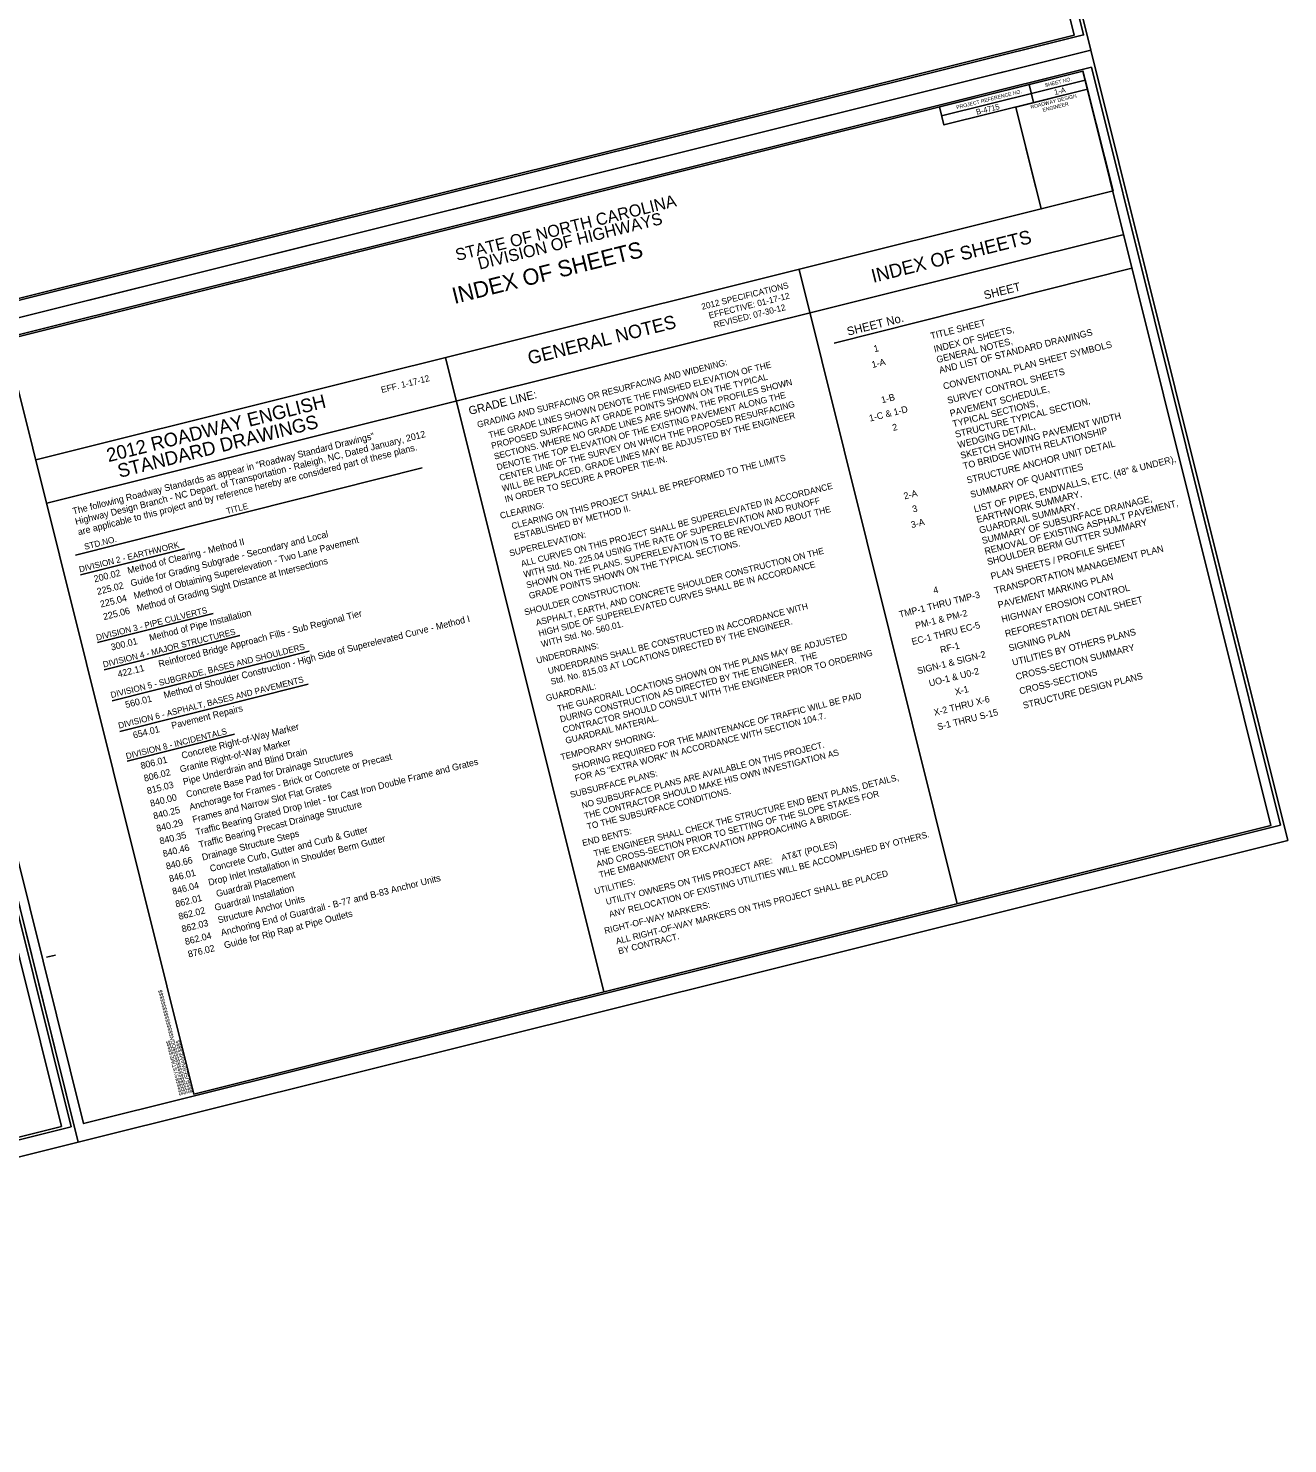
# Model space of a CAD drawing. Extents: x 1030323 to 1034123, y 654802 to 657751.
# Drawn here: x 1032422 to 1034123, y 654802 to 656713 of the extents above; entities that cross this region are included whole.
import ezdxf

# ---------------------------------------------------------------- set-up
doc = ezdxf.new("R2010")
doc.units = 0
for name, color, linetype in [('Default', 7, 'Continuous'), ('Old_Level_40', 7, 'Continuous'), ('Sheet Cutting Line CELL', 7, 'Continuous'), ('Sheet Data Field CELL', 7, 'Continuous'), ('Sheet Plan CELL', 7, 'Continuous'), ('Sheet Plot Border Inside CELL', 7, 'Continuous'), ('Sheet Plot Border Outside CELL', 7, 'Continuous'), ('Sheet Summary CELL', 7, 'Continuous'), ('Sheet Symbology CELL', 7, 'Continuous')]:
    doc.layers.add(name, color=color, linetype=linetype)

msp = doc.modelspace()

# ---------------------------------------------------------------- linework, layer by layer
at = {"layer": 'Old_Level_40'}
for p, q in [((1033510.2, 656288.1), (1033912.5, 656389.2)), ((1032485.4, 656001.8), (1032953.8, 656119.5)), ((1032492.1, 655975.1), (1032632.6, 656010.4)), ((1032515.1, 655883.6), (1032671.3, 655922.8)), ((1032524.3, 655847.1), (1032707.4, 655893.1)), ((1032534.8, 655805), (1032801.1, 655871.9)), ((1032545.2, 655763.8), (1032799.6, 655827.7)), ((1032555.3, 655723.6), (1032700.3, 655760))]:
    msp.add_line(p, q, dxfattribs=at)
at = {"layer": 'Sheet Cutting Line CELL'}
for p, q in [((1032223.1, 656276.4), (1033857.1, 656683.8)), ((1033857.1, 656683.8), (1032223.1, 656276.4)), ((1032223.1, 656276.4), (1032489.2, 655209.1)), ((1032489.2, 655209.1), (1034123.2, 655616.5)), ((1030855.2, 654801.7), (1032489.2, 655209.1))]:
    msp.add_line(p, q, dxfattribs=at)
at = {"layer": 'Sheet Plan CELL'}
for p, q in [((1033755.7, 656606.8), (1033783.1, 656497.7)), ((1032431.8, 656130.6), (1033790.2, 656469.3)), ((1032446.6, 656071.9), (1033902, 656434.8)), ((1033676.8, 655531), (1033463.1, 656387.8)), ((1033199.1, 655411.9), (1032985.5, 656268.7))]:
    msp.add_line(p, q, dxfattribs=at)
msp.add_lwpolyline([(1033755.7, 656606.8), (1033852.7, 656631.2), (1033887.2, 656493.7), (1033790.2, 656469.3)], close=True, dxfattribs=at)
at = {"layer": 'Sheet Plot Border Inside CELL'}
for points in [[(1033592, 657728.3), (1031975, 657325.1), (1032230.3, 656301.4), (1033847.3, 656704.5)], [(1033858.1, 656661), (1032241.1, 656257.8), (1032496.4, 655234), (1034113.4, 655637.2)], [(1030862.4, 654826.7), (1032479.4, 655229.8), (1032224.1, 656253.6), (1030607.1, 655850.4)]]:
    msp.add_lwpolyline(points, close=True, dxfattribs=at)
at = {"layer": 'Sheet Plot Border Outside CELL'}
for points in [[(1033590.9, 657751.2), (1031957, 657343.8), (1032223.1, 656276.4), (1033857.1, 656683.8)], [(1033857.1, 656683.8), (1032223.1, 656276.4), (1032489.2, 655209.1), (1034123.2, 655616.5)], [(1030855.2, 654801.7), (1032489.2, 655209.1), (1032223.1, 656276.4), (1030589.1, 655869)]]:
    msp.add_lwpolyline(points, close=True, dxfattribs=at)
at = {"layer": 'Sheet Summary CELL'}
for p, q in [((1033655.5, 656594.9), (1033849.6, 656643.3)), ((1033658.6, 656582.8), (1033852.7, 656631.2)), ((1033773.8, 656637.3), (1033779.9, 656613)), ((1033140, 656387.8), (1033140, 656387.8)), ((1032446.1, 655458.6), (1032458.2, 655461.6)), ((1032645.2, 655273.8), (1032645.2, 655273.8)), ((1032645.2, 655273.8), (1032645.2, 655273.8)), ((1032645.2, 655273.8), (1032645.2, 655273.8)), ((1032645.2, 655273.8), (1032645.2, 655273.8)), ((1032645.2, 655273.8), (1032645.2, 655273.8)), ((1032645.2, 655273.8), (1032645.2, 655273.8))]:
    msp.add_line(p, q, dxfattribs=at)
for points in [[(1033580.5, 657722.8), (1032125.1, 657359.9), (1032379.1, 656341.1), (1033834.5, 656704)], [(1033846.6, 656655.5), (1032391.2, 656292.6), (1032645.2, 655273.8), (1034100.6, 655636.7)], [(1033652.5, 656607.1), (1033846.6, 656655.5), (1033852.7, 656631.2), (1033658.6, 656582.8)]]:
    msp.add_lwpolyline(points, close=True, dxfattribs=at)
for points in [[(1032512.5, 656374.4), (1032512.5, 656374.4)], [(1032778.6, 655307), (1032778.6, 655307)]]:
    msp.add_lwpolyline(points, dxfattribs=at)
at = {"layer": 'Sheet Symbology CELL'}
msp.add_lwpolyline([(1032212.6, 656248.1), (1030757.2, 655885.2), (1031011, 654867.4), (1032466.4, 655230.3)], close=True, dxfattribs=at)

# ---------------------------------------------------------------- texts
at = {"layer": 'Default'}
for s, height, p in [('SHEET', 11.35, (1033714.1, 656347.1)), ('SHEET No.', 11.35, (1033529.3, 656298.1)), ('TITLE SHEET', 9, (1033641.8, 656293.3)), ('INDEX OF SHEETS,', 9, (1033646.2, 656275.5)), ('AND LIST OF STANDARD DRAWINGS', 9, (1033653.4, 656247)), ('1', 9, (1033565, 656275.8)), ('GENERAL NOTES,', 9, (1033649.8, 656261.2)), ('CONVENTIONAL PLAN SHEET SYMBOLS', 9, (1033658.8, 656225.3)), ('GRADING AND SURFACING OR RESURFACING AND WIDENING:  ', 8.5, (1033029.2, 656173.7)), ('THE GRADE LINES SHOWN DENOTE THE FINISHED ELEVATION OF THE', 8.5, (1033044.7, 656159.6)), ('1-A', 9, (1033562.3, 656254.5)), ('PROPOSED SURFACING AT GRADE POINTS SHOWN ON THE TYPICAL', 8.5, (1033048.3, 656145.2)), ('SECTIONS. WHERE NO GRADE LINES ARE SHOWN, THE PROFILES SHOWN', 8.5, (1033052, 656130.7)), ('SURVEY CONTROL SHEETS', 9, (1033664.5, 656206.1)), ('GRADE LINE:  ', 11.124, (1033018.1, 656191.1)), ('DENOTE THE TOP ELEVATION OF THE EXISTING PAVEMENT ALONG THE', 8.5, (1033055.6, 656116.3)), ('1-B', 9, (1033575.1, 656206.8)), ('PAVEMENT SCHEDULE,', 9, (1033667.9, 656188.8)), ('CENTER LINE OF THE SURVEY ON WHICH THE PROPOSED RESURFACING', 8.5, (1033059.2, 656101.9)), ('1-C & 1-D', 9, (1033558.8, 656182.1)), ('TYPICAL SECTIONS,', 9, (1033671.5, 656174.5)), ('STRUCTURE TYPICAL SECTION,', 9, (1033675, 656160.3)), ('WILL BE REPLACED. GRADE LINES MAY BE ADJUSTED BY THE ENGINEER', 8.5, (1033062.8, 656087.5)), ('SKETCH SHOWING PAVEMENT WIDTH', 9, (1033682.2, 656131.8)), ('2', 9, (1033590.2, 656169.4)), ('WEDGING DETAIL,', 9, (1033678.6, 656146.1)), ('TO BRIDGE WIDTH RELATIONSHIP', 9, (1033685.8, 656117.6)), ('STRUCTURE ANCHOR UNIT DETAIL', 9, (1033690.6, 656098.3)), ('IN ORDER TO SECURE A PROPER TIE-IN.', 8.5, (1033066.5, 656073)), ('CLEARING ON THIS PROJECT SHALL BE PREFORMED TO THE LIMITS', 8.5, (1033075.6, 656036.7)), ('SUMMARY OF QUANTITIES', 9, (1033695.5, 656079)), ('LIST OF PIPES, ENDWALLS, ETC. (48" & UNDER), ', 9, (1033700.3, 656059.4)), ('ALL CURVES ON THIS PROJECT SHALL BE SUPERELEVATED IN ACCORDANCE', 8.5, (1033088.4, 655985.9)), ('2-A', 9, (1033605.5, 656077)), ('EARTHWORK SUMMARY,', 9, (1033703.9, 656045.2)), ('CLEARING:', 8.5, (1033060.1, 656050.8)), ('ESTABLISHED BY METHOD II.', 8.5, (1033079.2, 656022.2)), ('WITH Std. No. 225.04 USING THE RATE OF SUPERELEVATION AND RUNOFF', 8.5, (1033092, 655971.4)), ('SHOWN ON THE PLANS. SUPERELEVATION IS TO BE REVOLVED ABOUT THE', 8.5, (1033095.6, 655957)), ('3', 9, (1033617.2, 656059.3)), ('GUARDRAIL SUMMARY,', 9, (1033707.5, 656030.9)), ('SUMMARY OF SUBSURFACE DRAINAGE,', 9, (1033711.1, 656016.7)), ('REMOVAL OF EXISTING ASPHALT PAVEMENT,', 9, (1033714.7, 656002.5)), ('3-A', 9, (1033615.2, 656038.2)), ('SHOULDER BERM GUTTER SUMMARY', 9, (1033718.2, 655988.2)), ('SUPERELEVATION:', 8.5, (1033072.8, 656000)), ('GRADE POINTS SHOWN ON THE TYPICAL SECTIONS.', 8.5, (1033099.2, 655942.6)), ('ASPHALT, EARTH, AND CONCRETE SHOULDER CONSTRUCTION ON THE', 8.5, (1033108.4, 655906.2)), ('PLAN SHEETS / PROFILE SHEET', 9, (1033723.1, 655968.8)), ('TRANSPORTATION MANAGEMENT PLAN', 9, (1033727.9, 655949.4)), ('HIGH SIDE OF SUPERELEVATED CURVES SHALL BE IN ACCORDANCE', 8.5, (1033112, 655891.8)), ('PAVEMENT MARKING PLAN', 9, (1033732.7, 655930)), ('SHOULDER CONSTRUCTION:', 8.5, (1033092.9, 655920.4)), ('TMP-1 THRU TMP-3', 9, (1033599.2, 655917.2)), ('4', 9, (1033645.4, 655949.5)), ('HIGHWAY EROSION CONTROL', 9, (1033737.6, 655910.6)), ('UNDERDRAINS SHALL BE CONSTRUCTED IN ACCORDANCE WITH', 8.5, (1033124.8, 655841)), ('REFORESTATION DETAIL SHEET', 9, (1033742.4, 655891.2)), ('Std. No. 815.03 AT LOCATIONS DIRECTED BY THE ENGINEER.', 8.5, (1033128.4, 655826.6)), ('PM-1 & PM-2', 9, (1033621.2, 655902.1)), ('WITH Std. No. 560.01.', 8.5, (1033115.6, 655877.4)), ('THE GUARDRAIL LOCATIONS SHOWN ON THE PLANS MAY BE ADJUSTED', 8.5, (1033137.5, 655790.2)), ('EC-1 THRU EC-5', 9, (1033616.3, 655880.3)), ('SIGNING PLAN', 9, (1033747.3, 655871.8)), ('UTILITIES BY OTHERS PLANS', 9, (1033752.1, 655852.4)), ('UNDERDRAINS:', 8.5, (1033109.2, 655855.1)), ('RF-1 ', 9, (1033654.8, 655869.3)), ('CROSS-SECTION SUMMARY', 9, (1033756.9, 655833)), ('DURING CONSTRUCTION AS DIRECTED BY THE ENGINEER.  THE', 8.5, (1033141.1, 655775.8)), ('CONTRACTOR SHOULD CONSULT WITH THE ENGINEER PRIOR TO ORDERING', 8.5, (1033144.8, 655761.3)), ('SIGN-1 & SIGN-2', 9, (1033623.8, 655840.9)), ('UO-1 & U0-2', 9, (1033639.6, 655824.3)), ('CROSS-SECTIONS', 9, (1033761.8, 655813.6)), ('STRUCTURE DESIGN PLANS', 9, (1033766.6, 655794.2)), ('GUARDRAIL: ', 8.5, (1033122, 655804.3)), ('X-1', 9, (1033674.7, 655812.5)), ('SHORING REQUIRED FOR THE MAINTENANCE OF TRAFFIC WILL BE PAID', 8.5, (1033157.5, 655710.5)), ('X-2 THRU X-6', 9, (1033646.1, 655784.7)), ('GUARDRAIL MATERIAL.', 8.5, (1033148.4, 655746.9)), ('FOR AS "EXTRA WORK" IN ACCORDANCE WITH SECTION 104.7.', 8.5, (1033161.2, 655696.1)), ('S-1 THRU S-15', 9, (1033650.9, 655765.3)), ('TEMPORARY SHORING:', 8.5, (1033142, 655724.7)), ('NO SUBSURFACE PLANS ARE AVAILABLE ON THIS PROJECT.', 8.5, (1033170.3, 655659.7)), ('THE CONTRACTOR SHOULD MAKE HIS OWN INVESTIGATION AS', 8.5, (1033173.9, 655645.3)), ('SUBSURFACE PLANS:  ', 8.5, (1033154.8, 655673.9)), ('THE ENGINEER SHALL CHECK THE STRUCTURE END BENT PLANS, DETAILS,', 8.5, (1033186.7, 655594.5)), ('TO THE SUBSURFACE CONDITIONS.', 8.5, (1033177.5, 655630.9)), ('AND CROSS-SECTION PRIOR TO SETTING OF THE SLOPE STAKES FOR', 8.5, (1033190.3, 655580.1)), ('THE EMBANKMENT OR EXCAVATION APPROACHING A BRIDGE.', 8.5, (1033193.9, 655565.7)), ('END BENTS:', 8.5, (1033171.2, 655608.7))]:
    msp.add_text(s, height=height, rotation=14.1042, dxfattribs=at).set_placement(p)
at = {"layer": 'Old_Level_40'}
for s, height, p in [('2012 SPECIFICATIONS', 8.343, (1033332.2, 656333.1)), ('EFFECTIVE: 01-17-12', 8.343, (1033342.1, 656321.2)), ('REVISED: 07-30-12', 8.343, (1033348.6, 656308.5)), ('EFF. 1-17-12', 8.512, (1032899.4, 656220.7)), ('The following Roadway Standards as appear in "Roadway Standard Drawings"', 9, (1032482.6, 656056.6)), ('Highway Design Branch - NC Depart. of Transportation - Raleigh, NC, Dated January, 2012', 9, (1032486.1, 656042.6)), ('are applicable to this project and by reference hereby are considered part of these plans.', 9, (1032489.6, 656028.5)), ('STD.NO.                                                  TITLE', 8.243, (1032498.3, 656008.9)), ('225.02   Guide for Grading Subgrade - Secondary and Local', 9, (1032515.5, 655948)), ('DIVISION 2 - EARTHWORK', 8.243, (1032491.3, 655978.4)), ('200.02   Method of Clearing - Method II', 9, (1032511.3, 655965)), ('225.04   Method of Obtaining Superelevation - Two Lane Pavement', 9, (1032519.8, 655931)), ('225.06   Method of Grading Sight Distance at Intersections', 9, (1032524, 655914)), ('DIVISION 3 - PIPE CULVERTS', 8.243, (1032514.4, 655886.3)), ('300.01     Method of Pipe Installation', 9, (1032534.3, 655872.8)), ('422.11      Reinforced Bridge Approach Fills - Sub Regional Tier', 9, (1032543.5, 655836.5)), ('560.01     Method of Shoulder Construction - High Side of Superelevated Curve - Method I', 9, (1032553.8, 655795.2)), ('DIVISION 4 - MAJOR STRUCTURES', 8.243, (1032523.5, 655849.9)), ('DIVISION 5 - SUBGRADE, BASES AND SHOULDERS', 8.243, (1032533.9, 655808.7)), ('DIVISION 6 - ASPHALT, BASES AND PAVEMENTS', 8.243, (1032544.3, 655767.4)), ('654.01     Pavement Repairs', 9, (1032564.2, 655754)), ('DIVISION 8 - INCIDENTALS', 8.243, (1032554.6, 655726.2)), ('806.01      Concrete Right-of-Way Marker', 9, (1032574.6, 655712.8)), ('806.02    Granite Right-of-Way Marker', 9, (1032578.9, 655695.8)), ('815.03    Pipe Underdrain and Blind Drain', 9, (1032583.1, 655678.9)), ('840.00    Concrete Base Pad for Drainage Structures', 9, (1032587.4, 655661.9)), ('840.25    Anchorage for Frames - Brick or Concrete or Precast', 9, (1032591.7, 655644.9)), ('840.35    Traffic Bearing Grated Drop Inlet - for Cast Iron Double Frame and Grates', 9, (1032600.2, 655611)), ('840.29    Frames and Narrow Slot Flat Grates', 9, (1032595.9, 655628)), ('840.46    Traffic Bearing Precast Drainage Structure', 9, (1032604.5, 655594)), ('840.66    Drainage Structure Steps', 9, (1032608.7, 655577)), ('846.01      Concrete Curb, Gutter and Curb & Gutter', 9, (1032613, 655560.1)), ('ANY RELOCATION OF EXISTING UTILITIES WILL BE ACCOMPLISHED BY OTHERS.', 8.5, (1033207.3, 655512.3)), ('846.04    Drop Inlet Installation in Shoulder Berm Gutter', 9, (1032617.3, 655543.1)), ('UTILITY OWNERS ON THIS PROJECT ARE:    AT&T (POLES)', 8.5, (1033203.1, 655529.3)), ('862.01      Guardrail Placement', 9, (1032621.5, 655526.1)), ('862.04    Anchoring End of Guardrail - B-77 and B-83 Anchor Units', 9, (1032634.3, 655475.2)), ('ALL RIGHT-OF-WAY MARKERS ON THIS PROJECT SHALL BE PLACED', 8.5, (1033216.5, 655476)), ('862.02    Guardrail Installation', 9, (1032625.8, 655509.1)), ('UTILITIES:  ', 8.5, (1033187.6, 655543.5)), ('862.03    Structure Anchor Units', 9, (1032630, 655492.2)), ('RIGHT-OF-WAY MARKERS:  ', 8.5, (1033201, 655490.1)), ('876.02    Guide for Rip Rap at Pipe Outlets', 9, (1032638.6, 655458.2)), ('BY CONTRACT.', 8.5, (1033219.8, 655462.7))]:
    msp.add_text(s, height=height, rotation=14.1042, dxfattribs=at).set_placement(p)
at = {"layer": 'Sheet Data Field CELL'}
for s, p in [('1-A', (1033808.7, 656623.1)), ('B-4715', (1033703.1, 656596.5))]:
    msp.add_text(s, height=7.5, rotation=14, dxfattribs=at).set_placement(p)
at = {"layer": 'Sheet Plan CELL'}
for s, p in [('ROADWAY DESIGN', (1033776.3, 656604.4)), ('ENGINEER', (1033792.6, 656600.4))]:
    msp.add_text(s, height=5, rotation=14.1042, dxfattribs=at).set_placement(p)
at = {"layer": 'Sheet Summary CELL'}
for s, height, rotation, p in [('SHEET NO.', 5, 14, (1033795.7, 656633.7)), ('PROJECT REFERENCE NO.', 5, 14, (1033676.1, 656604)), ('STATE OF NORTH CAROLINA', 16.25, 14, (1033000.9, 656399)), ('DIVISION OF HIGHWAYS', 16.25, 14, (1033031.3, 656387.3)), ('INDEX OF SHEETS', 18.444, 14.1042, (1033563.2, 656369.4)), ('INDEX OF SHEETS', 21.95, 14, (1032997.4, 656340.9)), ('GENERAL NOTES', 18.077, 14.1042, (1033098.9, 656258.9)), ('2012 ROADWAY ENGLISH', 18.444, 14.1042, (1032530, 656127.3)), ('STANDARD DRAWINGS', 18.444, 14.1042, (1032544.9, 656106.1)), ('$$$$$$$$$$$$$$$$DGN$$$$$$$$$$$$$$$$', 5.25, 104, (1032637.2, 655274.2)), ('$$$$$$SYSTIME$$$$$', 5.25, 104, (1032631.3, 655272.8)), ('$$$$USERNAME$$$$', 5.25, 104, (1032643.6, 655275.8))]:
    msp.add_text(s, height=height, rotation=rotation, dxfattribs=at).set_placement(p)

doc.saveas('drawing.dxf')
